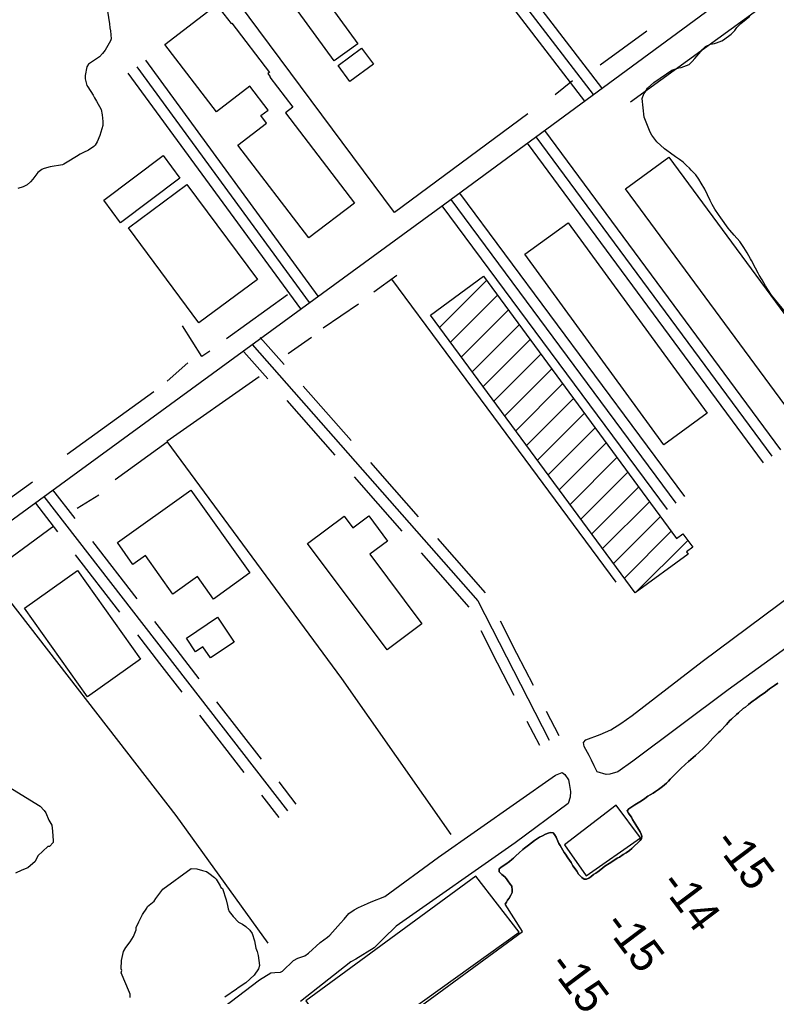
# Model space of a CAD drawing. Extents: x 3683613 to 3738215, y 469626 to 495384.
# Drawn here: x 3691288 to 3692332, y 490192 to 491540 of the extents above; entities that cross this region are included whole.
import ezdxf

# ---------------------------------------------------------------- set-up
doc = ezdxf.new("R2010")
doc.units = 0
for name, color, linetype in [('V-BLDG-OTLN', 7, 'Continuous'), ('V-CHAN-DOCK', 7, 'Continuous'), ('V-LEVE-TOET', 7, 'Continuous'), ('V-ROAD-CNTR', 7, 'Continuous'), ('V-SITE-VEGE', 7, 'Continuous'), ('V-TOPO-SHOR', 7, 'Continuous'), ('V-TOPO-SPOT', 7, 'Continuous')]:
    doc.layers.add(name, color=color, linetype=linetype)

msp = doc.modelspace()

# ---------------------------------------------------------------- linework, layer by layer
at = {"layer": 'V-BLDG-OTLN'}
for p, q in [((3691867.4, 491115), (3691932.2, 491179.8)), ((3691882.4, 491094.7), (3691947.2, 491159.5)), ((3691897.4, 491074.3), (3691962.2, 491139.1)), ((3691912.4, 491054), (3691977.2, 491118.8)), ((3691927.4, 491033.6), (3691992.2, 491098.4)), ((3691942.4, 491013.2), (3692007.2, 491078.1)), ((3691957.4, 490992.9), (3692022.2, 491057.7)), ((3691972.4, 490972.5), (3692037.2, 491037.4)), ((3691987.4, 490952.2), (3692052.2, 491017)), ((3692002.4, 490931.8), (3692067.2, 490996.7)), ((3692017.4, 490911.5), (3692082.2, 490976.3)), ((3692032.4, 490891.1), (3692097.2, 490956)), ((3692047.4, 490870.8), (3692112.2, 490935.6)), ((3692062.4, 490850.4), (3692127.2, 490915.2)), ((3692077.4, 490830.1), (3692142.2, 490894.9)), ((3692092.4, 490809.7), (3692157.2, 490874.5)), ((3692107.4, 490789.4), (3692172.2, 490854.2)), ((3692122.4, 490769), (3692187.2, 490833.8)), ((3692137.4, 490748.6), (3692209.8, 490821.1))]:
    msp.add_line(p, q, dxfattribs=at)
for points in [[(3691617.7, 491694.3), (3691754.6, 491506.6), (3691722.1, 491482.9), (3691585.3, 491670.6)], [(3691588.9, 491366.5), (3691628.6, 491396.8), (3691620.5, 491407.4), (3691630.8, 491415.2), (3691605.6, 491448.1), (3691559.3, 491412.7), (3691488.2, 491505.8), (3691559.7, 491560.5), (3691579.7, 491534.4), (3691580.6, 491535.1), (3691632.6, 491467.1), (3691630.2, 491465.4), (3691633.6, 491460.9), (3691633.1, 491460.5), (3691664.8, 491419.1), (3691654.6, 491411.4), (3691749.8, 491286.8), (3691686.8, 491238.6)], [(3691759.7, 491500.7), (3691776.1, 491478.4), (3691743.5, 491454.5), (3691727.2, 491476.8)], [(3691485.7, 491352.2), (3691509.1, 491320.9), (3691427.2, 491259.5), (3691403.8, 491290.8)], [(3692184, 491350.2), (3692451.3, 490987.4), (3692391.5, 490943.4), (3692124.2, 491306.2)], [(3691438, 491252.7), (3691518.7, 491312.5), (3691615.9, 491181.4), (3691535.2, 491121.6)], [(3692044.8, 491259.6), (3692236.5, 490996.8), (3692176.8, 490953.2), (3691985.2, 491216)], [(3691927.9, 491185.7), (3692194.5, 490823.9), (3692203, 490830.2), (3692216.7, 490811.7), (3692208.1, 490805.5), (3692210.4, 490802.3), (3692137.5, 490748.5), (3691854.9, 491132)], [(3691605.7, 490776.1), (3691555.5, 490740.2), (3691533.4, 490771.1), (3691499.4, 490746.8), (3691461.4, 490800.2), (3691444.2, 490787.9), (3691422.7, 490818.2), (3691524, 490890.5)], [(3691842.8, 490705.8), (3691795.1, 490670.1), (3691685.3, 490816.9), (3691735.5, 490854.4), (3691747.5, 490838.3), (3691769.6, 490854.9), (3691795.6, 490820.2), (3691771, 490801.9)], [(3691454.6, 490657), (3691381.4, 490605), (3691294.4, 490727.4), (3691367.6, 490779.4)], [(3691560.9, 490714.9), (3691583.7, 490680.7), (3691551.1, 490658.9), (3691540.8, 490674.3), (3691530.6, 490667.5), (3691518, 490686.3)]]:
    msp.add_lwpolyline(points, close=True, dxfattribs=at)
at = {"layer": 'V-CHAN-DOCK'}
for points in [[(3692039.9, 490400.9), (3692069.5, 490358.3), (3692144.6, 490410.3), (3692110.9, 490455.5), (3692039.9, 490400.9)], [(3691682.7, 490185.7), (3691738.1, 490108.5), (3691977.4, 490280.4), (3691917.3, 490357.6), (3691682.7, 490185.7)]]:
    msp.add_lwpolyline(points, dxfattribs=at)
at = {"layer": 'V-LEVE-TOET'}
for points in [[(3692069.1, 490545.9), (3692088.8, 490553), (3692103.8, 490559.4), (3692117.5, 490568.2), (3692133.4, 490579.5), (3692229.8, 490654), (3692399.1, 490780.2), (3692581.2, 490917.7), (3692781.3, 491071.1)], [(3692817.6, 491015.3), (3692548.9, 490819.4), (3692265.6, 490615), (3692133.9, 490516.5), (3692113.4, 490501.8), (3692102.2, 490498.6), (3692097.3, 490498), (3692084.8, 490501.7), (3692080.9, 490510), (3692077.1, 490517.8), (3692073.7, 490524.3), (3692071.3, 490528.5), (3692067.1, 490536.8), (3692066.2, 490541.9), (3692069.1, 490545.9)], [(3691423.9, 490065.7), (3691618.9, 490214.5), (3691634.3, 490224.1), (3691640, 490224.7), (3691647.9, 490225), (3691650.6, 490226.7), (3691665.8, 490241.4), (3691671.9, 490244.6), (3691681.6, 490247.8), (3691686.3, 490251.2), (3691702.5, 490265.9), (3691712.5, 490273.3), (3691716, 490276.3), (3691730.6, 490292.7), (3691735.6, 490298.4), (3691742, 490306.1), (3691749.3, 490311), (3691755.3, 490314.2), (3691767.7, 490319.8), (3691772.8, 490322.1), (3691792, 490329.4), (3691866.1, 490383.8), (3692027.4, 490497.2), (3692036.5, 490500.6), (3692040.3, 490497.9), (3692045.5, 490490.7), (3692046.1, 490485.6), (3692048.1, 490474.4), (3692047.5, 490466.8), (3692044.8, 490457.9), (3691971.7, 490403.8), (3691807.3, 490288.8), (3691789.8, 490271.4), (3691777.1, 490258.6), (3691752, 490243), (3691745, 490239.4), (3691675.4, 490184.6)]]:
    msp.add_lwpolyline(points, dxfattribs=at)
at = {"layer": 'V-ROAD-CNTR'}
for points in [[(3692067.7, 491427.4), (3691820.9, 491749.5), (3691827.2, 491797.8)], [(3692079.6, 491436.5), (3691836.5, 491753.7), (3691842, 491795.9)], [(3692091.5, 491445.6), (3691852.2, 491757.9), (3691856.9, 491793.9)], [(3688673, 488939.5), (3688673, 488939.5), (3689744.9, 489727.8), (3690837.2, 490528.1), (3691874.8, 491285.9), (3692249.8, 491561.6)], [(3691700, 491158.3), (3691461.9, 491483.8)], [(3691675.8, 491140.6), (3691437.7, 491466.1)], [(3691687.9, 491149.4), (3691449.8, 491475)], [(3692012.4, 491387.1), (3692338, 490946.2)], [(3692000.4, 491378.2), (3692325.9, 490937.3)], [(3691988.3, 491369.3), (3692313.9, 490928.3)], [(3691882.7, 491291.7), (3692193.6, 490872.6)], [(3691894.7, 491300.6), (3692205.6, 490881.6)], [(3691870.6, 491282.8), (3692181.5, 490863.7)], [(3691619.7, 491101.3), (3691652.8, 491063.8)], [(3691608.5, 491091.4), (3691920, 490737.8), (3692018.4, 490545.2)], [(3691597.2, 491081.5), (3691630.3, 491044)], [(3691679.2, 491033.8), (3691745.3, 490958.8)], [(3691656.7, 491014), (3691722.8, 490938.9)], [(3691771.8, 490928.7), (3691804.8, 490891.2)], [(3691749.3, 490908.9), (3691782.3, 490871.4)], [(3691333.2, 490890.8), (3691363.8, 490851.3)], [(3691804.8, 490891.2), (3691837.9, 490853.7)], [(3691309.5, 490872.5), (3691340.1, 490832.9)], [(3691321.3, 490881.7), (3691657.3, 490447.7)], [(3691782.3, 490871.4), (3691815.4, 490833.9)], [(3691388.3, 490819.7), (3691449.5, 490740.6)], [(3691864.3, 490823.7), (3691930.4, 490748.7)], [(3691841.8, 490803.9), (3691907.9, 490728.8)], [(3691364.6, 490801.3), (3691425.8, 490722.2)], [(3691951, 490710.1), (3691973.7, 490665.6)], [(3691474, 490709), (3691504.6, 490669.4)], [(3691924.3, 490696.5), (3691947, 490651.9)], [(3691450.3, 490690.6), (3691480.9, 490651.1)], [(3691504.6, 490669.4), (3691535.2, 490629.9)], [(3691973.7, 490665.6), (3691996.5, 490621.1)], [(3691480.9, 490651.1), (3691511.5, 490611.5)], [(3691947, 490651.9), (3691969.8, 490607.4)], [(3691559.7, 490598.3), (3691620.9, 490519.2)], [(3691536, 490579.9), (3691597.2, 490500.8)], [(3692014.7, 490585.5), (3692031.8, 490552)], [(3691988, 490571.8), (3692005.1, 490538.3)], [(3691645.4, 490487.6), (3691669.2, 490456.8)], [(3691621.7, 490469.2), (3691645.5, 490438.5)]]:
    msp.add_lwpolyline(points, dxfattribs=at)
at = {"layer": 'V-SITE-VEGE'}
for points in [[(3691367.7, 491616), (3691373.1, 491609.7), (3691377.7, 491605.2), (3691382.2, 491600.8), (3691389, 491594.5), (3691392, 491590.3), (3691398.8, 491581.4), (3691405, 491563.9), (3691408.9, 491551.8), (3691411.7, 491534), (3691412.4, 491528.7)], [(3692344.5, 491136.6), (3692325.7, 491159.8), (3692317, 491172.7), (3692312.7, 491180.9), (3692308.4, 491187.4), (3692307.1, 491189.8), (3692303.5, 491196.7), (3692297.7, 491207.5), (3692296.7, 491209.8), (3692291.8, 491218.1), (3692287.5, 491225.5), (3692284.5, 491229.7), (3692282, 491233.5), (3692274.1, 491242.4), (3692267.9, 491249.3), (3692265.8, 491252.1), (3692255.5, 491266.2), (3692252.3, 491271.1), (3692247.2, 491278.4), (3692243.6, 491284.8), (3692241, 491290.5), (3692233.3, 491306.1), (3692228.6, 491314.4), (3692225.4, 491319.6), (3692221.2, 491325.6), (3692214.6, 491332.1), (3692212.2, 491334.8), (3692208.2, 491338.4), (3692203.7, 491343.1), (3692198.6, 491346.8), (3692193.1, 491350.6), (3692186.1, 491355.5), (3692181.2, 491359.3), (3692177.6, 491361.8), (3692167.4, 491371.3), (3692160.1, 491380.6), (3692158, 491384.6), (3692150.5, 491403), (3692149.8, 491405.3), (3692147, 491431.3), (3692149.5, 491437.5), (3692150.9, 491440), (3692154.5, 491445.5), (3692163.2, 491453.2), (3692171.6, 491459.2), (3692187.9, 491470.3), (3692197.4, 491473.5), (3692200.6, 491473.9), (3692212, 491478.2), (3692216, 491482.3), (3692219.8, 491486.5), (3692230.7, 491499.3), (3692234.3, 491502.7), (3692241.3, 491505.9), (3692247, 491507), (3692249.5, 491507.8), (3692256.9, 491510.6), (3692259.3, 491512.1), (3692269.8, 491520), (3692274.7, 491524.9), (3692277.6, 491528.9), (3692283.3, 491534.5), (3692287.9, 491538.1), (3692295.8, 491544.7)], [(3691412.4, 491528.7), (3691413.3, 491524.7), (3691414, 491513.5), (3691413.3, 491510.9), (3691405.8, 491498), (3691402.2, 491493.3), (3691398.2, 491488.4), (3691383, 491478.4), (3691380.7, 491474.6), (3691378, 491462.7), (3691378, 491458), (3691380.6, 491448.9), (3691382.1, 491447), (3691389.3, 491435.6), (3691391.2, 491432), (3691394, 491427.4), (3691400.2, 491415.8), (3691401.7, 491408.4), (3691402.6, 491399.5), (3691402.4, 491394), (3691401.4, 491389.1), (3691398.5, 491380), (3691394.9, 491371.3), (3691392, 491366.6), (3691390.3, 491364.9), (3691382.7, 491359.6), (3691376.1, 491356.6), (3691371.5, 491354.2), (3691366.2, 491351.2), (3691353.5, 491343.3), (3691348.9, 491340.6), (3691346.8, 491339.5), (3691330.1, 491336.7), (3691325, 491335.6), (3691320.3, 491334.1), (3691318.2, 491333), (3691313.1, 491329), (3691305.8, 491319.8), (3691302.6, 491316.2), (3691298, 491311.9), (3691292.7, 491309.2), (3691285.3, 491306.8)], [(3691271.9, 490481.5), (3691316.2, 490454.2), (3691321.6, 490448.4), (3691323.8, 490445), (3691328, 490434.7), (3691332.3, 490427.8), (3691333.2, 490419.9), (3691333.9, 490406.3), (3691333.9, 490404.1), (3691329.2, 490398.6), (3691326.9, 490398.6), (3691313, 490385.5), (3691309.4, 490377.7), (3691299, 490369), (3691291, 490365.9), (3691281.9, 490361.6)], [(3691440.3, 490190.1), (3691440.4, 490194.6), (3691439.4, 490196.9), (3691427.8, 490224.3), (3691429, 490227.6), (3691427.9, 490229.9), (3691428.3, 490241.2), (3691430.9, 490253.5), (3691434.4, 490259), (3691440.3, 490266.8), (3691445, 490274.5), (3691448.7, 490283.4), (3691448.8, 490286.8), (3691452.4, 490294.6), (3691457.2, 490304.6), (3691463.1, 490313.4), (3691464.3, 490315.7), (3691473.5, 490323.3), (3691475.9, 490326.6), (3691485.3, 490339.8), (3691524.5, 490368), (3691532.4, 490367.8), (3691540.2, 490365.3), (3691545.8, 490364), (3691549.1, 490361.6), (3691556.8, 490355.8), (3691559, 490353.5), (3691564.4, 490344.3), (3691565.4, 490342), (3691567.6, 490340.8), (3691572.8, 490324.9), (3691574.8, 490316.9), (3691575.8, 490312.4), (3691576.9, 490308.9), (3691582.3, 490302), (3691589.9, 490293.9), (3691595.5, 490291.5), (3691599.9, 490288), (3691605.4, 490283.3), (3691608.7, 490278.7), (3691611.7, 490268.5), (3691613.7, 490258.2), (3691615.8, 490253.7), (3691616.8, 490248), (3691618.6, 490234.4), (3691617.4, 490229.9), (3691611.5, 490221.1), (3691599.9, 490210.2), (3691589.5, 490203.7), (3691587.2, 490201.5), (3691571.1, 490190.7)]]:
    msp.add_lwpolyline(points, dxfattribs=at)
at = {"layer": 'V-TOPO-SHOR'}
for p, q in [((3692487.1, 491684.4), (3692130.9, 491426.2)), ((3692153.4, 491523.8), (3692089, 491476.9)), ((3692050.7, 491455.3), (3692026.7, 491436.1)), ((3691808.2, 491186.7), (3691776.5, 491163.6)), ((3691657.5, 491159.9), (3691573.3, 491099.5)), ((3691755.4, 491147), (3691706.5, 491114.2)), ((3691690.4, 491101.4), (3691658.3, 491078.6)), ((3691520.1, 491066), (3691491.2, 491041.1)), ((3691473, 491026), (3691353.6, 490939.7)), ((3691491.4, 490956.7), (3691419.4, 490904.6)), ((3691397.3, 490883.4), (3691367.1, 490865.2))]:
    msp.add_line(p, q, dxfattribs=at)
for points in [[(3691989.3, 491409.7), (3691805.3, 491273.7), (3691589.8, 491563.1), (3691444.1, 491773.2)], [(3692110.9, 490763.6), (3691951.3, 490979.1), (3691801.6, 491181.9)], [(3691550.5, 491082.5), (3691539.3, 491074.8), (3691512.4, 491117.5)], [(3691618.2, 491046.7), (3691490.9, 490957.4), (3691732, 490630.4), (3691883.1, 490415.3)], [(3691305.4, 490901.5), (3691209, 490832), (3691199, 490833.5), (3691132.3, 490927.6)], [(3691334.8, 490840.7), (3691241.9, 490772.5), (3691088.9, 490664.6)], [(3691244.8, 490774.6), (3691503.2, 490441.3), (3691630.3, 490265.1)], [(3692334.1, 490624.2), (3692329.7, 490620.8), (3692322.9, 490616.1), (3692317, 490611.8), (3692308.6, 490605.6), (3692303.1, 490601.6), (3692300.1, 490599.7), (3692296.6, 490596.7), (3692293.8, 490594.5), (3692289.4, 490590.9), (3692286.4, 490589), (3692279.9, 490583.2), (3692277.4, 490580.7), (3692270.4, 490574.5), (3692268.1, 490572.6), (3692263.4, 490567.1), (3692254.4, 490557.9), (3692252.1, 490555.8), (3692247.8, 490551.5), (3692244.5, 490547.9), (3692237.1, 490539.8), (3692234.4, 490537.1), (3692231.8, 490534.3), (3692225.5, 490528.6), (3692220.6, 490524.1), (3692214.1, 490518.6), (3692210.9, 490516), (3692206.7, 490512.4), (3692200, 490505.8), (3692194.9, 490500.7), (3692188.6, 490494.3), (3692185.4, 490491.3), (3692183.1, 490488.8), (3692180.4, 490486.2), (3692174.9, 490481.3), (3692169.6, 490477.3), (3692165.6, 490474.3), (3692162.2, 490472.1), (3692158.2, 490470), (3692155, 490468.1), (3692150.8, 490464.9), (3692147.6, 490462.5), (3692143.6, 490460), (3692136.7, 490456.1), (3692132.6, 490453.2), (3692128.6, 490450.4), (3692126.5, 490448), (3692128.2, 490444.5), (3692130.2, 490441.5), (3692132.1, 490439), (3692133.8, 490436), (3692135.9, 490432), (3692138.1, 490428.6), (3692141.7, 490422.7), (3692144, 490418.7), (3692145.5, 490415.7), (3692146.4, 490412.6), (3692146, 490409.4), (3692144.3, 490406.8), (3692141.1, 490403.4), (3692136.5, 490399.4), (3692132.7, 490395.8), (3692129.5, 490393), (3692124.9, 490390), (3692120.9, 490387.4), (3692115.8, 490384), (3692112.6, 490382.3), (3692105, 490377.6), (3692101.2, 490375.3), (3692095.3, 490371.2), (3692092.6, 490368.9), (3692089.8, 490367), (3692085.6, 490363.6), (3692083.1, 490361.6), (3692079.9, 490359.7), (3692076.1, 490356.5), (3692073.2, 490354.8), (3692070, 490353.7), (3692066.8, 490353.7), (3692063.6, 490355.8), (3692061.3, 490357.9), (3692059.2, 490360.3), (3692056.6, 490364.7), (3692054.3, 490367.9), (3692051.5, 490372.1), (3692049.1, 490376.3), (3692046.6, 490379.7), (3692044.2, 490383.1), (3692041.2, 490387.9), (3692039.1, 490390.4), (3692035.5, 490396.8), (3692033.6, 490400), (3692031.9, 490402.7), (3692030.4, 490406.1), (3692028.2, 490411.4), (3692026.1, 490415), (3692024.2, 490417.5), (3692020.6, 490417.7), (3692017.2, 490417), (3692013.6, 490415.5)], [(3692180.4, 490486.2), (3692183.1, 490488.8), (3692185.4, 490491.3), (3692188.6, 490494.3), (3692194.9, 490500.7), (3692200, 490505.8), (3692206.7, 490512.4), (3692210.9, 490516), (3692214.1, 490518.6), (3692220.6, 490524.1), (3692225.5, 490528.6), (3692231.8, 490534.3), (3692234.4, 490537.1), (3692237.1, 490539.8), (3692244.5, 490547.9), (3692247.8, 490551.5), (3692252.1, 490555.8), (3692254.4, 490557.9), (3692263.4, 490567.1), (3692268.1, 490572.6), (3692270.4, 490574.5), (3692277.4, 490580.7), (3692279.9, 490583.2), (3692286.4, 490589), (3692289.4, 490590.9), (3692293.8, 490594.5), (3692296.6, 490596.7), (3692300.1, 490599.7), (3692303.1, 490601.6), (3692308.6, 490605.6), (3692317, 490611.8), (3692322.9, 490616.1), (3692329.7, 490620.8), (3692334.1, 490624.2)], [(3691739.1, 490103.3), (3691981.8, 490281.1), (3691957.9, 490318.9), (3691959.6, 490321.9), (3691961.3, 490324.4), (3691963.4, 490327.4), (3691965.5, 490331.2), (3691967.4, 490335), (3691967.6, 490338.4), (3691967.1, 490343.7), (3691965, 490346.7), (3691961.8, 490351.1), (3691959.9, 490353.9), (3691957.3, 490356.6), (3691953.5, 490360), (3691949.6, 490363.6), (3691949.4, 490367.6), (3691951.9, 490369.5), (3691955.3, 490371.8), (3691958.9, 490374.2), (3691963.8, 490377.8), (3691966.9, 490380.6), (3691969.3, 490382.5), (3691972.8, 490385.7), (3691977.3, 490389.7), (3691982.1, 490394.2), (3691984.7, 490396.3), (3691990.1, 490400.4), (3691994.4, 490403.8), (3691998.4, 490406.8), (3692002.4, 490409.8), (3692005.1, 490411.3), (3692009.6, 490413.4), (3692013.6, 490415.5), (3692017.2, 490417), (3692020.6, 490417.7), (3692024.2, 490417.5), (3692026.1, 490415), (3692028.2, 490411.4), (3692030.4, 490406.1), (3692031.9, 490402.7), (3692033.6, 490400), (3692035.5, 490396.8), (3692039.1, 490390.4), (3692041.2, 490387.9), (3692044.2, 490383.1), (3692046.6, 490379.7), (3692049.1, 490376.3), (3692051.5, 490372.1), (3692054.3, 490367.9), (3692056.6, 490364.7), (3692059.2, 490360.3), (3692061.3, 490357.9), (3692063.6, 490355.8), (3692066.8, 490353.7), (3692070, 490353.7), (3692073.2, 490354.8), (3692076.1, 490356.5), (3692079.9, 490359.7), (3692083.1, 490361.6), (3692085.6, 490363.6), (3692089.8, 490367), (3692092.6, 490368.9), (3692095.3, 490371.2), (3692101.2, 490375.3), (3692105, 490377.6), (3692112.6, 490382.3), (3692115.8, 490384), (3692120.9, 490387.4), (3692124.9, 490390), (3692129.5, 490393), (3692132.7, 490395.8), (3692136.5, 490399.4), (3692141.1, 490403.4), (3692144.3, 490406.8), (3692146, 490409.4), (3692146.4, 490412.6), (3692145.5, 490415.7), (3692144, 490418.7), (3692141.7, 490422.7), (3692138.1, 490428.6), (3692135.9, 490432), (3692133.8, 490436), (3692132.1, 490439), (3692130.2, 490441.5), (3692128.2, 490444.5), (3692126.5, 490448), (3692128.6, 490450.4), (3692132.6, 490453.2), (3692136.7, 490456.1), (3692143.6, 490460), (3692147.6, 490462.5), (3692150.8, 490464.9), (3692155, 490468.1), (3692158.2, 490470), (3692162.2, 490472.1), (3692165.6, 490474.3), (3692169.6, 490477.3), (3692174.9, 490481.3), (3692180.4, 490486.2)], [(3692013.6, 490415.5), (3692009.6, 490413.4), (3692005.1, 490411.3), (3692002.4, 490409.8), (3691998.4, 490406.8), (3691994.4, 490403.8), (3691990.1, 490400.4), (3691984.7, 490396.3), (3691982.1, 490394.2), (3691977.3, 490389.7), (3691972.8, 490385.7), (3691969.3, 490382.5), (3691966.9, 490380.6), (3691963.8, 490377.8), (3691958.9, 490374.2), (3691955.3, 490371.8), (3691951.9, 490369.5), (3691949.4, 490367.6), (3691949.6, 490363.6), (3691953.5, 490360), (3691957.3, 490356.6), (3691959.9, 490353.9), (3691961.8, 490351.1), (3691965, 490346.7), (3691967.1, 490343.7), (3691967.6, 490338.4), (3691967.4, 490335), (3691965.5, 490331.2), (3691963.4, 490327.4), (3691961.3, 490324.4), (3691959.6, 490321.9), (3691957.9, 490318.9)]]:
    msp.add_lwpolyline(points, dxfattribs=at)

# ---------------------------------------------------------------- texts
at = {"layer": 'V-TOPO-SPOT'}
for s, p in [('-15', (3692244.6, 490404)), ('-14', (3692170.1, 490346.5)), ('-15', (3692092.7, 490290.3)), ('-15', (3692016.2, 490234.1))]:
    msp.add_text(s, height=45, rotation=306.9347, dxfattribs=at).set_placement(p)

doc.saveas('drawing.dxf')
